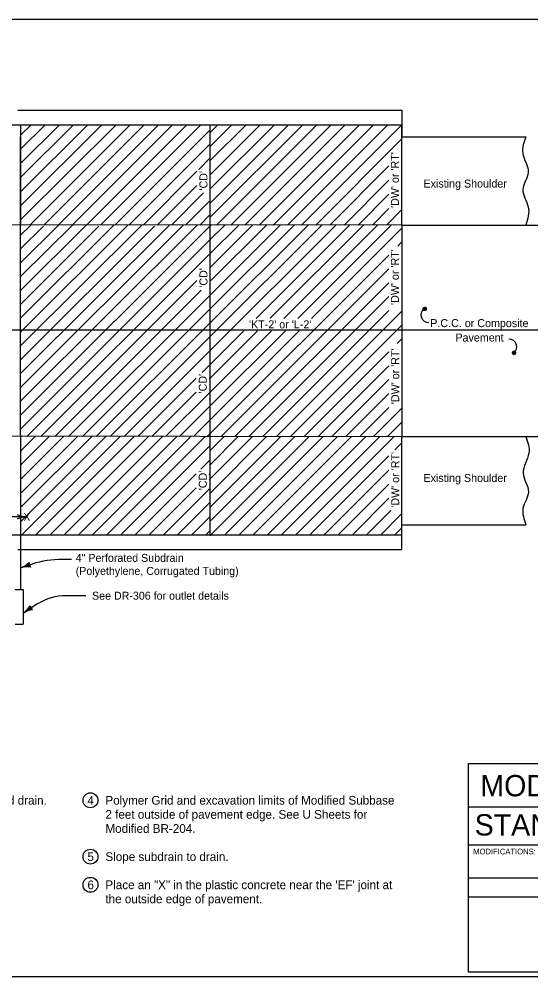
# Model space of a CAD drawing. Extents: x 9234 to 81668, y 5635 to 15999.
# Drawn here: x 23096 to 24175, y 13780 to 15800 of the extents above; entities that cross this region are included whole.
import ezdxf

# ---------------------------------------------------------------- set-up
doc = ezdxf.new("R2010")
doc.units = 0
for name, color, linetype in [('Alignment', 7, 'Continuous'), ('Level 61', 7, 'Continuous'), ('PS_BOLT', 7, 'Continuous'), ('PS_DIM', 7, 'Continuous'), ('SurEdgeShoulderUnpaved', 7, 'Continuous')]:
    doc.layers.add(name, color=color, linetype=linetype)

msp = doc.modelspace()

# ---------------------------------------------------------------- linework, layer by layer
msp.add_line((22356.3, 15577.8), (23903.1, 15577.8))
at = {"layer": 'Level 61'}
msp.add_lwpolyline([(21596.3, 15800.4), (24731.3, 15800.4), (24731.3, 13780.4), (21596.3, 13780.4)], close=True, dxfattribs=at)
at = {"layer": 'PS_BOLT'}
for p, q in [((23903.1, 15413.8), (23903.1, 15455.4)), ((23903.1, 15366.2), (23903.1, 14920)), ((23434.2, 14920), (23498.2, 14983.9)), ((23463.5, 14920), (23498.2, 14954.7)), ((21917.1, 14923.2), (23903.1, 14920)), ((23492.7, 14920), (23498.2, 14925.5)), ((23112.4, 14750.5), (23081.1, 14750.5)), ((23206.8, 14660.9), (23187.1, 14660.9)), ((23135.2, 14567), (23104.7, 14547.8)), ((23236.8, 14584.3), (23195.3, 14584.3))]:
    msp.add_line(p, q, dxfattribs=at)
for centre, radius, start, end in [((23959.6, 15176.9), 16.5, 131.3092, 270), ((24128.5, 15109), 16.5, 311.309, 90), ((23187.1, 14455.3), 205.6, 90, 107.8594), ((23195.3, 14471.2), 113.1, 90, 122.0832)]:
    msp.add_arc(centre, radius, start, end, dxfattribs=at)
at = {"layer": 'PS_DIM'}
for p, q in [((23093.3, 15608.6), (23903.1, 15608.6)), ((23903.1, 15608.6), (23903.1, 15552.3)), ((23099.5, 15577.8), (23099.5, 15367.3)), ((23099.5, 15376.8), (23300.5, 15577.8)), ((23099.5, 15406.6), (23270.7, 15577.8)), ((23099.5, 15436.5), (23240.9, 15577.8)), ((23099.5, 15466.3), (23211, 15577.8)), ((23099.5, 15496.2), (23181.2, 15577.8)), ((23099.5, 15526), (23151.3, 15577.8)), ((23099.5, 15555.8), (23121.5, 15577.8)), ((23118.8, 15366.2), (23330.4, 15577.8)), ((23148.7, 15366.2), (23360.2, 15577.8)), ((23178.5, 15366.2), (23390.1, 15577.8)), ((23208.4, 15366.2), (23419.9, 15577.8)), ((23238.2, 15366.2), (23449.7, 15577.8)), ((23268.1, 15366.2), (23479.6, 15577.8)), ((23498.2, 15411.7), (23664.3, 15577.8)), ((23498.2, 15531.1), (23544.9, 15577.8)), ((23498.2, 15560.9), (23515, 15577.8)), ((23498.2, 15381.9), (23694.1, 15577.8)), ((23498.2, 15577.8), (23498.2, 14920)), ((23498.2, 15471.4), (23604.6, 15577.8)), ((23498.2, 15501.3), (23574.7, 15577.8)), ((23498.2, 15441.6), (23634.4, 15577.8)), ((23512.4, 15366.2), (23724, 15577.8)), ((23542.3, 15366.2), (23753.8, 15577.8)), ((23572.1, 15366.2), (23783.7, 15577.8)), ((23602, 15366.2), (23813.5, 15577.8)), ((23631.8, 15366.2), (23843.3, 15577.8)), ((23661.7, 15366.2), (23873.2, 15577.8)), ((23691.5, 15366.2), (23903, 15577.8)), ((23903.1, 15366.2), (23903.1, 15577.8)), ((23297.9, 15366.2), (23498.2, 15566.5)), ((23099.5, 15367.3), (23099.5, 15552.3)), ((23327.8, 15366.2), (23498.2, 15536.7)), ((23721.4, 15366.2), (23903.1, 15548)), ((23903.1, 15552.2), (24164.5, 15552.2)), ((23903.1, 15366.2), (23903.1, 15552.2)), ((23474.8, 15483.4), (23498.2, 15506.9)), ((23357.6, 15366.2), (23471, 15479.6)), ((23751.2, 15366.2), (23875.7, 15490.7)), ((23781.1, 15366.2), (23875.7, 15460.8)), ((23387.4, 15366.2), (23471, 15449.8)), ((23417.3, 15366.2), (23485.1, 15434)), ((23447.1, 15366.2), (23498.2, 15417.3)), ((23810.9, 15366.2), (23875.7, 15431)), ((23840.8, 15366.2), (23875.7, 15401.2)), ((23870.6, 15366.2), (23903.1, 15398.8)), ((23477, 15366.2), (23498.2, 15387.5)), ((23903.1, 15366.2), (21870.4, 15367.3)), ((23099.5, 14923.2), (23099.5, 15367.3)), ((23099.5, 14994.3), (23471.5, 15366.2)), ((23099.5, 15111.2), (23354.6, 15366.2)), ((23099.5, 15052.7), (23413, 15366.2)), ((23099.5, 15023.5), (23442.2, 15366.2)), ((23099.5, 15228.1), (23237.7, 15366.2)), ((23099.5, 15169.6), (23296.1, 15366.2)), ((23099.5, 15140.4), (23325.4, 15366.2)), ((23099.5, 15344.9), (23120.8, 15366.2)), ((23099.5, 15286.5), (23179.3, 15366.2)), ((23099.5, 15257.3), (23208.5, 15366.2)), ((23099.5, 14965.1), (23498.2, 15363.8)), ((23099.5, 15082), (23381.3, 15363.8)), ((23099.5, 15198.8), (23264.5, 15363.8)), ((23099.5, 15315.7), (23147.6, 15363.8)), ((23498.2, 15363.8), (23500.7, 15366.2)), ((23498.2, 15334.6), (23529.9, 15366.2)), ((23498.2, 15305.3), (23559.1, 15366.2)), ((23498.2, 15217.7), (23646.8, 15366.2)), ((23498.2, 15100.8), (23763.7, 15366.2)), ((23498.2, 15188.5), (23676, 15366.2)), ((23498.2, 15130), (23734.4, 15366.2)), ((23498.2, 15159.2), (23705.2, 15366.2)), ((23498.2, 15246.9), (23617.6, 15366.2)), ((23498.2, 15276.1), (23588.3, 15366.2)), ((23595.7, 15169.1), (23792.9, 15366.2)), ((23625.5, 15169.6), (23822.1, 15366.2)), ((23654.1, 15169.1), (23851.3, 15366.2)), ((23683.4, 15169.1), (23880.5, 15366.2)), ((23712.6, 15169.1), (23903.1, 15359.6)), ((23903.1, 15366.2), (24199.5, 15366.2)), ((23099.5, 14935.9), (23498.2, 15334.6)), ((23894.2, 15321.5), (23903.1, 15330.4)), ((23112.8, 14920), (23498.2, 15305.3)), ((23498.2, 14925.5), (23875.7, 15302.9)), ((23498.2, 15276.1), (23498.2, 15276.1)), ((23521.9, 14920), (23875.7, 15273.7)), ((23142, 14920), (23471, 15248.9)), ((23498.2, 15246.9), (23498.2, 15246.9)), ((23551.1, 14920), (23875.7, 15244.5)), ((23171.3, 14920), (23480.3, 15229)), ((23200.5, 14920), (23498.2, 15217.7)), ((23580.3, 14920), (23875.7, 15215.3)), ((23229.7, 14920), (23498.2, 15188.5)), ((23609.6, 14920), (23875.7, 15186.1)), ((23638.8, 14920), (23903.1, 15184.3)), ((23258.9, 14920), (23498.2, 15159.2)), ((23668, 14920), (23903.1, 15155.1)), ((22356.3, 15145.3), (24237.5, 15145.3)), ((23288.1, 14920), (23498.2, 15130)), ((23496.8, 15041), (23599, 15143.1)), ((23496.8, 15011.8), (23628.2, 15143.1)), ((23498.2, 14983.9), (23657.4, 15143.1)), ((23498.2, 14954.7), (23686.6, 15143.1)), ((23498.2, 15071.6), (23569.7, 15143.1)), ((23893.3, 15116.1), (23903.1, 15125.9)), ((23317.4, 14920), (23498.2, 15100.8)), ((23697.2, 14920), (23875.7, 15098.4)), ((23481.9, 15055.2), (23498.2, 15071.6)), ((23726.4, 14920), (23875.7, 15069.2)), ((23346.6, 14920), (23469.6, 15042.9)), ((23496.8, 15041), (23498.2, 15042.4)), ((23755.7, 14920), (23875.7, 15040)), ((23375.8, 14920), (23469.6, 15013.7)), ((23405, 14920), (23498.2, 15013.2)), ((23784.9, 14920), (23875.7, 15010.7)), ((23814.1, 14920), (23875.7, 14981.5)), ((23843.3, 14920), (23903.1, 14979.8)), ((23872.5, 14920), (23903.1, 14950.5)), ((23099.5, 14923.2), (23099.5, 14712.8)), ((23099.5, 14740.1), (23279.3, 14920)), ((23099.5, 14770), (23249.5, 14920)), ((23099.5, 14799.8), (23219.6, 14920)), ((23099.5, 14829.7), (23189.8, 14920)), ((23099.5, 14859.5), (23159.9, 14920)), ((23099.5, 14889.4), (23130.1, 14920)), ((23102, 14712.8), (23309.2, 14920)), ((23131.8, 14712.8), (23339, 14920)), ((23161.7, 14712.8), (23368.9, 14920)), ((23191.5, 14712.8), (23398.7, 14920)), ((23221.4, 14712.8), (23428.6, 14920)), ((23251.2, 14712.8), (23458.4, 14920)), ((23281.1, 14712.8), (23488.3, 14920)), ((23496.8, 14828.7), (23588.1, 14920)), ((23498.2, 14710.7), (23707.5, 14920)), ((23498.2, 14740.5), (23677.7, 14920)), ((23498.2, 14770.4), (23647.8, 14920)), ((23498.2, 14800.2), (23618, 14920)), ((23498.2, 14889.8), (23528.4, 14920)), ((23498.2, 14920), (23498.2, 14712.8)), ((23498.2, 14859.9), (23558.3, 14920)), ((23530.2, 14712.8), (23737.4, 14920)), ((23560, 14712.8), (23767.2, 14920)), ((23589.9, 14712.8), (23797, 14920)), ((23619.7, 14712.8), (23826.9, 14920)), ((23649.6, 14712.8), (23856.7, 14920)), ((23679.4, 14712.8), (23886.6, 14920)), ((23903.1, 14920), (24199.5, 14920)), ((23903.1, 14712.8), (23903.1, 14920)), ((23310.9, 14712.8), (23498.2, 14900.1)), ((23888.4, 14891.9), (23903.1, 14906.7)), ((23479.2, 14851.2), (23498.2, 14870.2)), ((23709.2, 14712.8), (23875.7, 14879.2)), ((23739.1, 14712.8), (23875.7, 14849.3)), ((23340.8, 14712.8), (23469.6, 14841.6)), ((23496.8, 14839), (23498.2, 14840.4)), ((23370.6, 14712.8), (23469.6, 14811.7)), ((23400.5, 14712.8), (23498.2, 14810.5)), ((23768.9, 14712.8), (23875.7, 14819.5)), ((23798.8, 14712.8), (23875.7, 14789.7)), ((23430.3, 14712.8), (23498.2, 14780.7)), ((23460.1, 14712.8), (23498.2, 14750.8)), ((23828.6, 14712.8), (23879.5, 14763.7)), ((23858.5, 14712.8), (23903.1, 14757.4)), ((23888.3, 14712.8), (23903.1, 14727.6)), ((23903.1, 14734), (24164.5, 14734)), ((23903.1, 14681.9), (23903.1, 14734)), ((22762.2, 14712.8), (23903.1, 14712.8)), ((23099.5, 14712.8), (23099.5, 14597.1)), ((23490, 14712.8), (23498.2, 14721)), ((23093.3, 14681.9), (23903.1, 14681.9)), ((23124.1, 14651), (23099.5, 14643)), ((23099.5, 14643), (23118.3, 14649.1)), ((23088.2, 14597.1), (23104.7, 14597.1)), ((23104.7, 14597.1), (23104.7, 14524.6)), ((23104.7, 14547.8), (23121.4, 14558.3)), ((23088.2, 14524.6), (23104.7, 14524.6))]:
    msp.add_line(p, q, dxfattribs=at)
for points in [[(23951.2, 15186), (23952.4, 15186.5), (23954.3, 15187.1), (23954.7, 15189), (23954.4, 15190.7), (23953.2, 15192.3), (23951.4, 15192.1), (23949.5, 15191.8), (23948.6, 15190.3), (23948.4, 15188.7), (23949.5, 15186.6), (23950.9, 15186.5), (23952.8, 15186.9), (23954.4, 15188.2), (23954.3, 15190), (23953.1, 15191.4), (23951.4, 15191.6), (23949.5, 15191.2), (23949.2, 15190.1), (23948.8, 15188.8), (23949.7, 15187.3), (23951.1, 15187.3), (23952.7, 15187.6), (23953.8, 15188.5), (23953.2, 15190), (23952, 15191), (23950.4, 15191), (23950, 15190.2), (23949.5, 15189.2), (23950.3, 15187.9), (23951.5, 15187.7), (23952.5, 15188.2), (23952.6, 15189.4), (23952.1, 15190.2), (23951, 15190.5), (23950.5, 15190.1), (23950.2, 15189.4), (23950.7, 15188.5), (23951.5, 15188.3), (23952.2, 15188.7), (23952.1, 15189.4), (23951.5, 15189.8), (23950.8, 15189.8), (23950.8, 15189.2), (23951.5, 15188.9)], [(24139.1, 15093.2), (24140.4, 15093.8), (24142.3, 15094.4), (24142.6, 15096.3), (24142.4, 15098), (24141.2, 15099.6), (24139.4, 15099.4), (24137.4, 15099.1), (24136.5, 15097.6), (24136.4, 15096), (24137.5, 15093.9), (24138.9, 15093.7), (24140.8, 15094.2), (24142.3, 15095.4), (24142.3, 15097.2), (24141.1, 15098.7), (24139.4, 15098.9), (24137.5, 15098.5), (24137.2, 15097.4), (24136.8, 15096.1), (24137.7, 15094.6), (24139.1, 15094.6), (24140.7, 15094.9), (24141.8, 15095.7), (24141.2, 15097.3), (24140, 15098.2), (24138.4, 15098.3), (24138, 15097.4), (24137.5, 15096.5), (24138.3, 15095.2), (24139.5, 15094.9), (24140.5, 15095.5), (24140.6, 15096.7), (24140, 15097.5), (24139, 15097.8), (24138.5, 15097.3), (24138.2, 15096.7), (24138.7, 15095.8), (24139.5, 15095.6), (24140.2, 15096), (24140.1, 15096.6), (24139.5, 15097.1), (24138.8, 15097), (24138.8, 15096.5), (24139.4, 15096.2)], [(23119.1, 14645.5), (23117.2, 14648.8), (23116.8, 14652.5), (23113.3, 14649.2), (23107.1, 14645.5), (23114.8, 14646.1), (23118.3, 14645.8), (23116.6, 14648.6), (23116.1, 14650.9), (23113.8, 14648.7), (23110.4, 14646.6), (23114.7, 14646.7), (23117, 14646.7), (23115.7, 14649.5), (23113.3, 14647.5), (23115.7, 14647.5), (23115.3, 14648.6), (23114.5, 14647.9)], [(23123, 14555), (23120.4, 14557.7), (23119.1, 14561.3), (23116.5, 14557.1), (23111.4, 14552.1), (23118.7, 14554.6), (23122.2, 14555.1), (23119.8, 14557.4), (23118.8, 14559.6), (23117.1, 14556.8), (23114.3, 14553.9), (23118.5, 14555.1), (23120.7, 14555.6), (23118.7, 14558.1), (23116.9, 14555.5), (23119.2, 14556.1), (23118.6, 14557.1), (23117.9, 14556.2)]]:
    msp.add_lwpolyline(points, dxfattribs=at)
for centre, radius in [((23951.4, 15189.3), 3.62), ((24139.4, 15096.6), 3.62), ((23246.7, 14152.8), 15.7), ((23246.7, 14033.9), 15.7), ((23246.7, 13974.5), 15.7)]:
    msp.add_circle(centre, radius, dxfattribs=at)
for centre, radius, start, end in [((23112.4, 14792.8), 42.3, 241.9275, 270), ((23112.4, 14708.3), 42.3, 90, 118.0725), ((23086.1, 14684.6), 43.7, 287.8585, 315.9309), ((23112.9, 14601.5), 43.7, 79.786, 107.8585), ((23134.4, 14654.3), 16.9, 180.1251, 215.5918), ((23081.5, 14584.8), 43.7, 302.0841, 330.1566), ((23127.9, 14510.8), 43.7, 94.0116, 122.0841), ((23135.7, 14567.3), 16.9, 194.3508, 229.8175)]:
    msp.add_arc(centre, radius, start, end, dxfattribs=at)
for points in [[(24164.5, 15552.2), (24157.6, 15517.8), (24169.3, 15476.9), (24157.9, 15441.2), (24169.3, 15404.4), (24164.5, 15366.2)], [(24164.5, 14920), (24170.6, 14885.1), (24158.5, 14843.1), (24169.6, 14803.1), (24158.2, 14768.5), (24164.5, 14734)]]:
    msp.add_spline(points, degree=3, dxfattribs=at)
at = {"layer": 'SurEdgeShoulderUnpaved'}
for p, q in [((24043.3, 14139.1), (24520.4, 14139.1)), ((24043.3, 14059), (24731.3, 14059)), ((24043.3, 13989), (24731.3, 13989)), ((24043.3, 13949), (24731.3, 13949)), ((24043.3, 13949), (24731.3, 13949))]:
    msp.add_line(p, q, dxfattribs=at)
msp.add_lwpolyline([(24043.3, 14230.4), (24731.3, 14230.4), (24731.3, 13790.4), (24043.3, 13790.4)], close=True, dxfattribs=at)

# ---------------------------------------------------------------- texts
at = {"layer": 'Alignment'}
for s, height, p in [('MODIFIED', 45, (24068.4, 14161.2)), ('MODIFICATIONS:', 12, (24053.3, 14038.7))]:
    msp.add_text(s, height=height, dxfattribs=at).set_placement(p)
at = {"layer": 'PS_BOLT'}
for s, height, p in [("'DW' or 'RT'", 16.884, (23896.8, 15402.2)), ("'CD'", 16.88, (23493.2, 15439)), ("'DW' or 'RT'", 16.884, (23896.8, 15197.5)), ("'CD'", 16.88, (23493.2, 15234)), ("'DW' or 'RT'", 16.884, (23897.4, 14988.3)), ("'CD'", 16.88, (23491.8, 15010.9)), ("'DW' or 'RT'", 16.884, (23897.4, 14769.9)), ("'CD'", 16.88, (23491.8, 14806.8))]:
    msp.add_text(s, height=height, rotation=90, dxfattribs=at).set_placement(p)
for s, height, p in [('Existing Shoulder', 16.884, (23948.5, 15445.2)), ("'KT-2' or 'L-2'", 16.884, (23580.8, 15148.2)), ('P.C.C. or Composite', 16.884, (23962.8, 15150.8)), ('Pavement', 16.88, (24015.8, 15120.4)), ('Existing Shoulder', 16.884, (23948.5, 14824.2)), ('X', 16, (23105.6, 14742.5)), ('4" Perforated Subdrain ', 16.8, (23215.6, 14655.7)), ('(Polyethylene, Corrugated Tubing)', 16.8, (23215.6, 14628.2)), ('See DR-306 for outlet details', 16.8, (23250, 14575.9)), ('Continue 4 inch Sloped Curb to edge of the bridge end drain.', 18.375, (22492.2, 14143.6)), ('4', 18.4, (23240.3, 14143.6)), ('Polymer Grid and excavation limits of Modified Subbase', 18.375, (23278.2, 14143.6)), ('2 feet outside of pavement edge. See U Sheets for', 18.375, (23278.2, 14113.9)), ('Modified BR-204.', 18.375, (23278.2, 14084.1)), ('5', 18.4, (23240.3, 14024.7)), ('Slope subdrain to drain.', 18.375, (23278.2, 14024.7)), ('6', 18.4, (23240.4, 13965.3)), ('Place an "X" in the plastic concrete near the \'EF\' joint at', 18.375, (23278.2, 13965.3)), ('the outside edge of pavement.', 18.375, (23278.2, 13935.6))]:
    msp.add_text(s, height=height, dxfattribs=at).set_placement(p)
at = {"layer": 'SurEdgeShoulderUnpaved'}
msp.add_text('STANDARD ROAD PLAN', height=45.001, dxfattribs=at).set_placement((24056.4, 14078.5))

doc.saveas('drawing.dxf')
